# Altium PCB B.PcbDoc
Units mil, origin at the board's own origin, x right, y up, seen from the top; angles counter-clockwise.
Board outline 3543 x 2362 mil, 4 copper layers (Top Layer, Internal Plane 1, Internal Plane 2, Bottom Layer); 34 components, 28 nets, 139 pads, 8 vias.
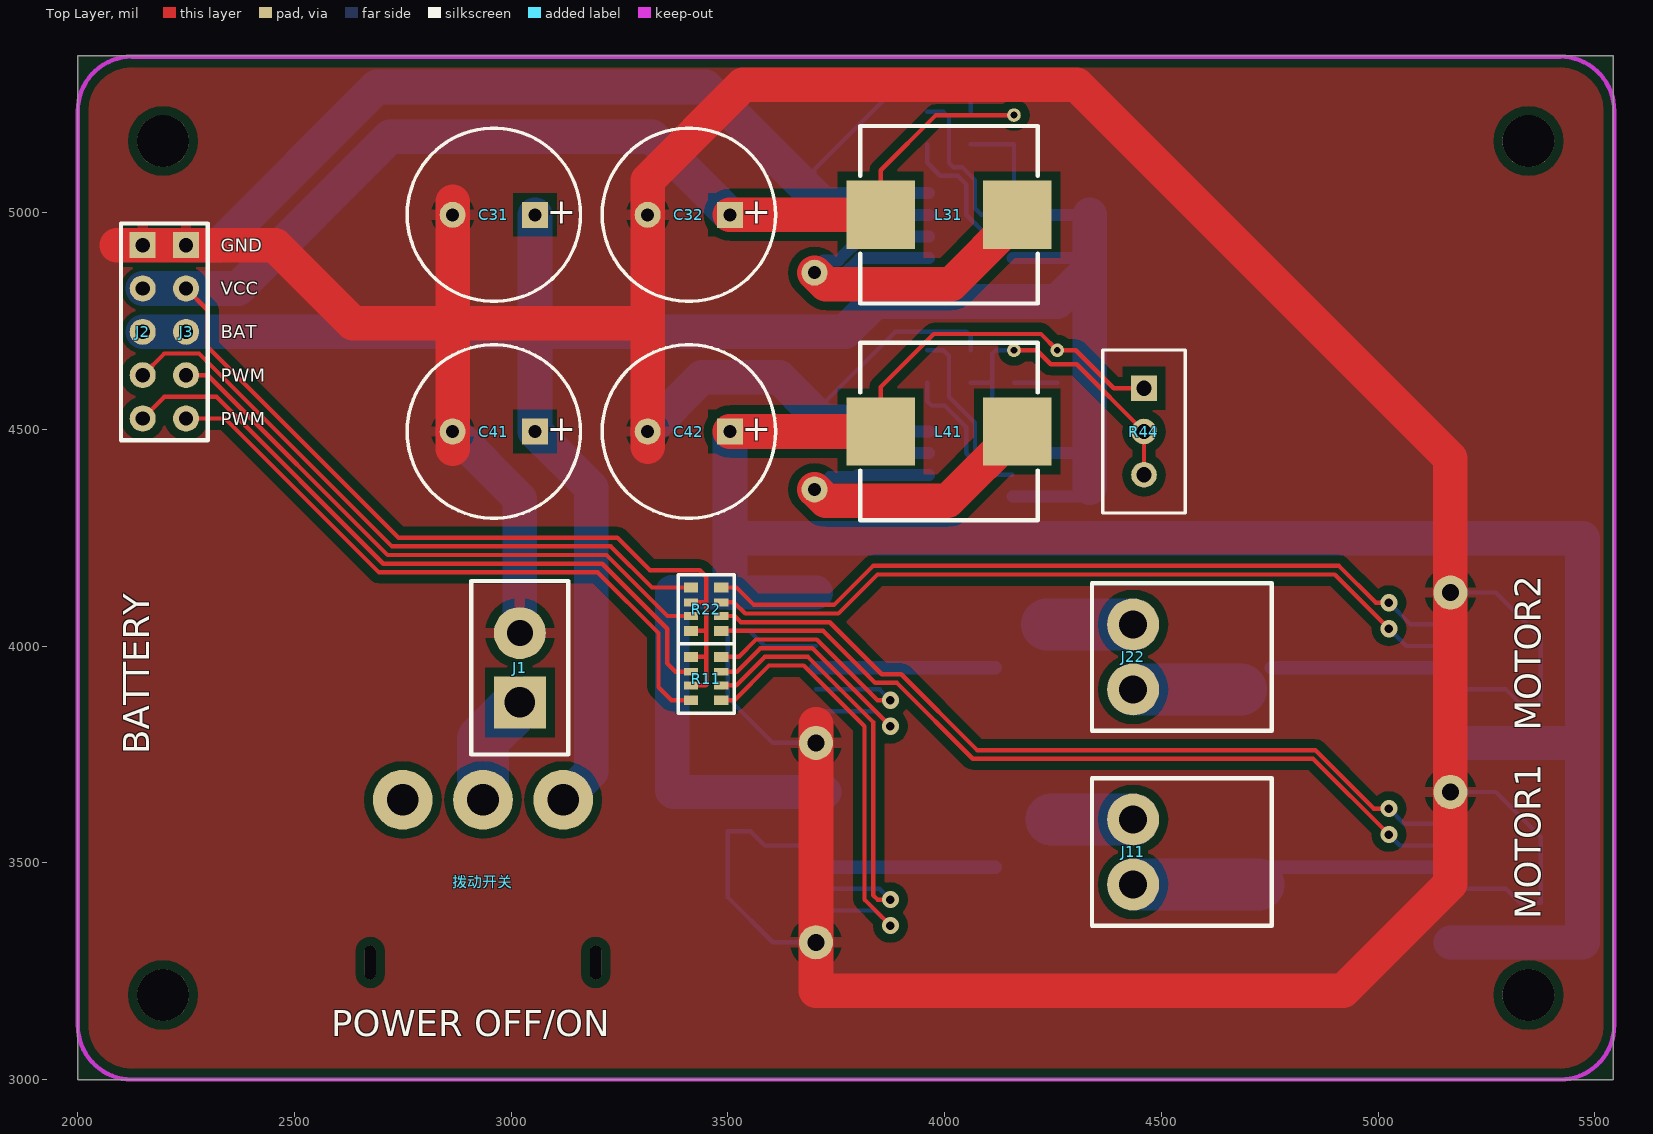
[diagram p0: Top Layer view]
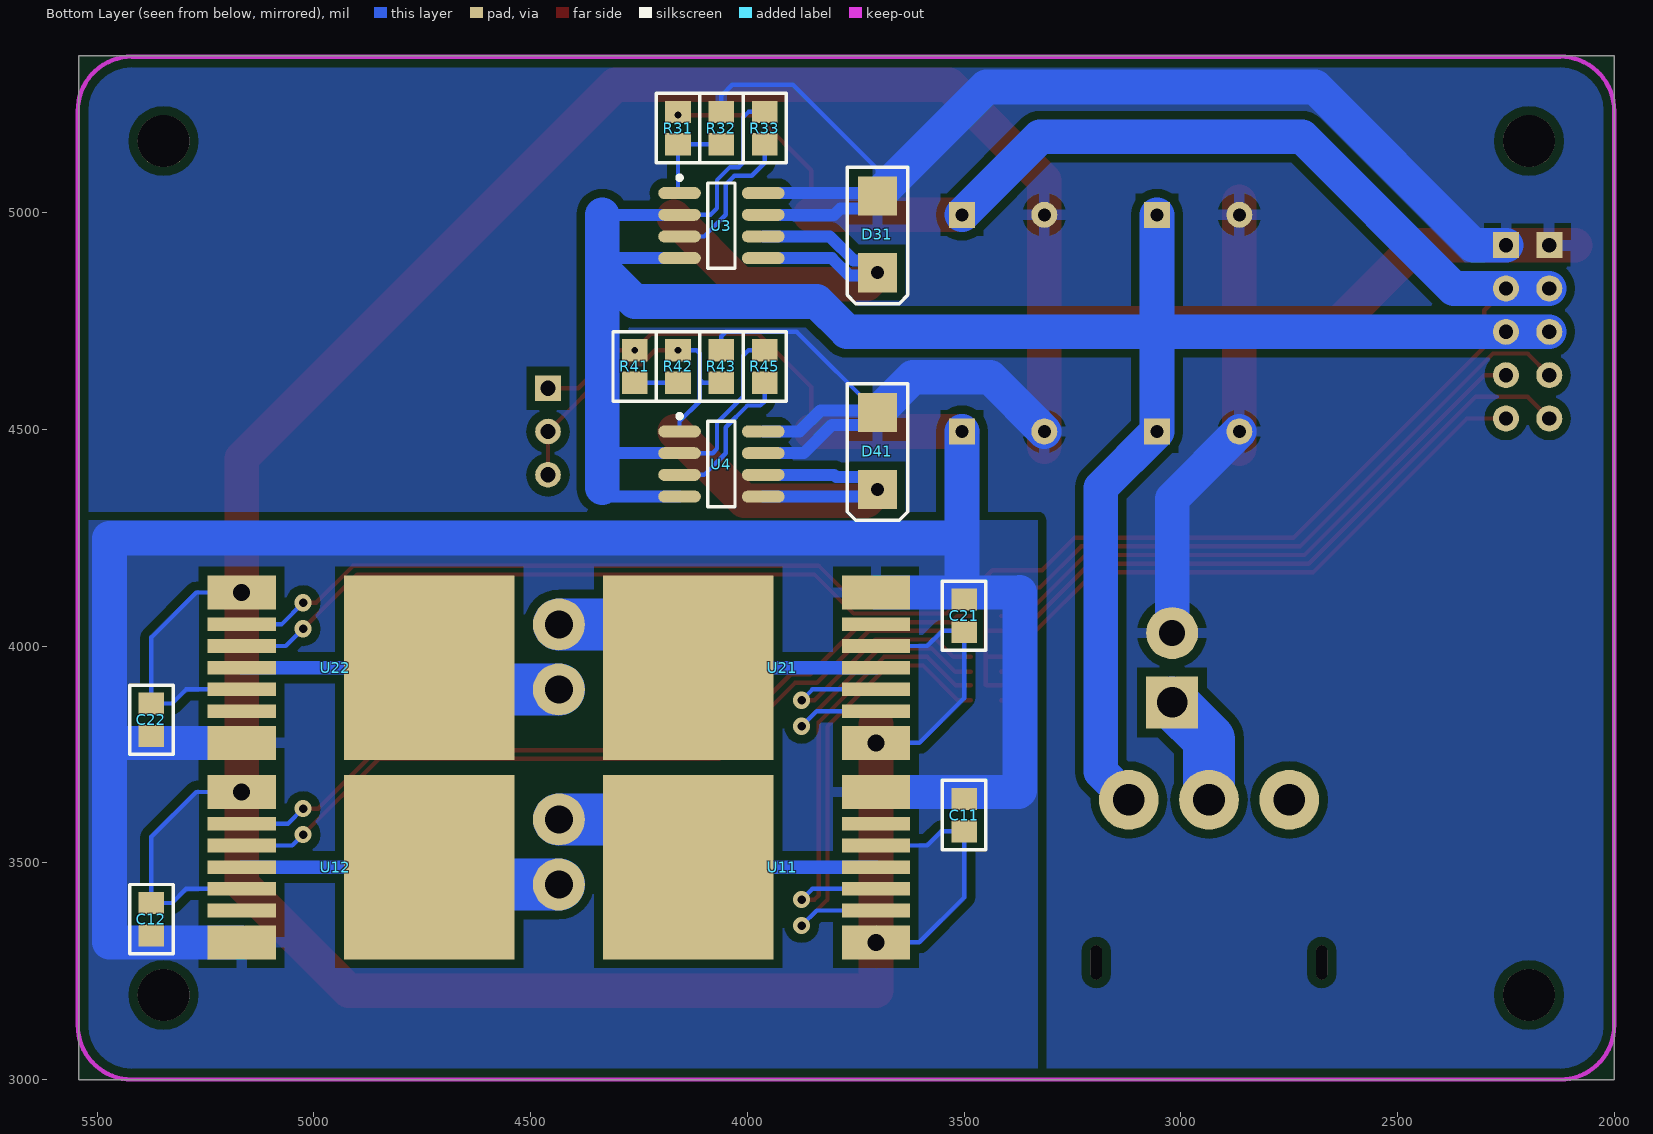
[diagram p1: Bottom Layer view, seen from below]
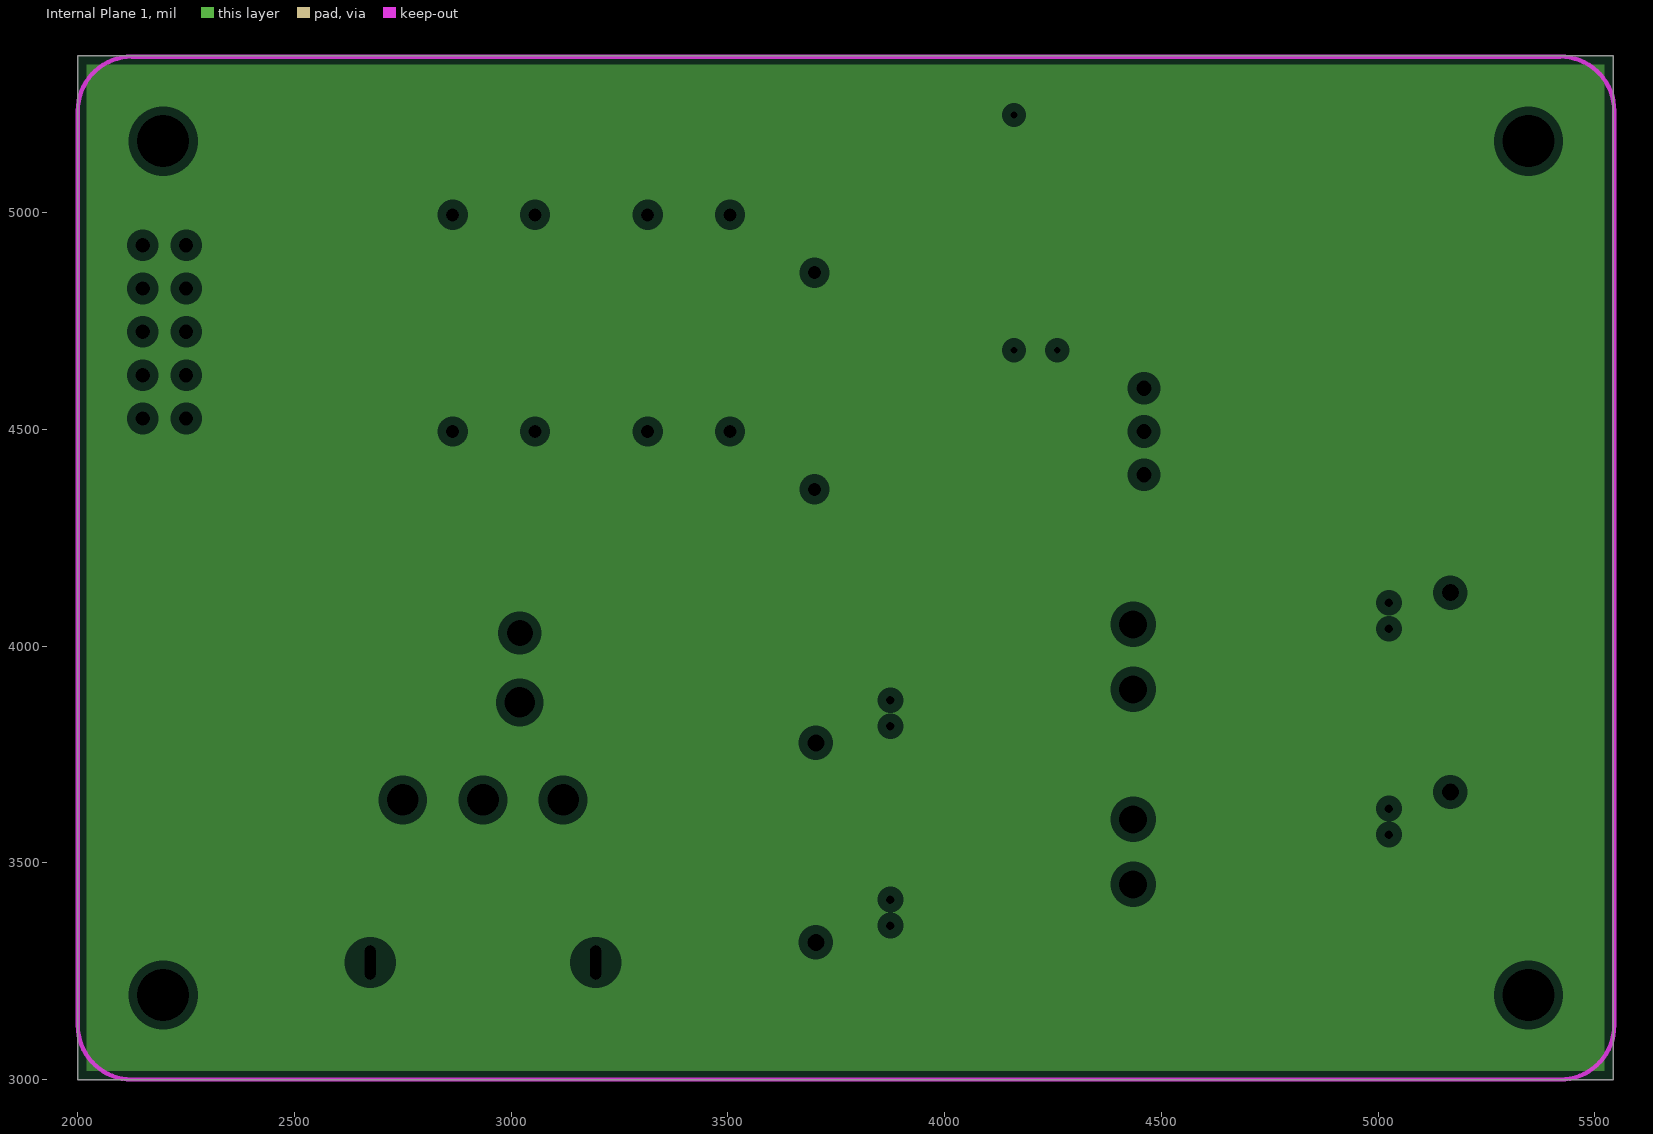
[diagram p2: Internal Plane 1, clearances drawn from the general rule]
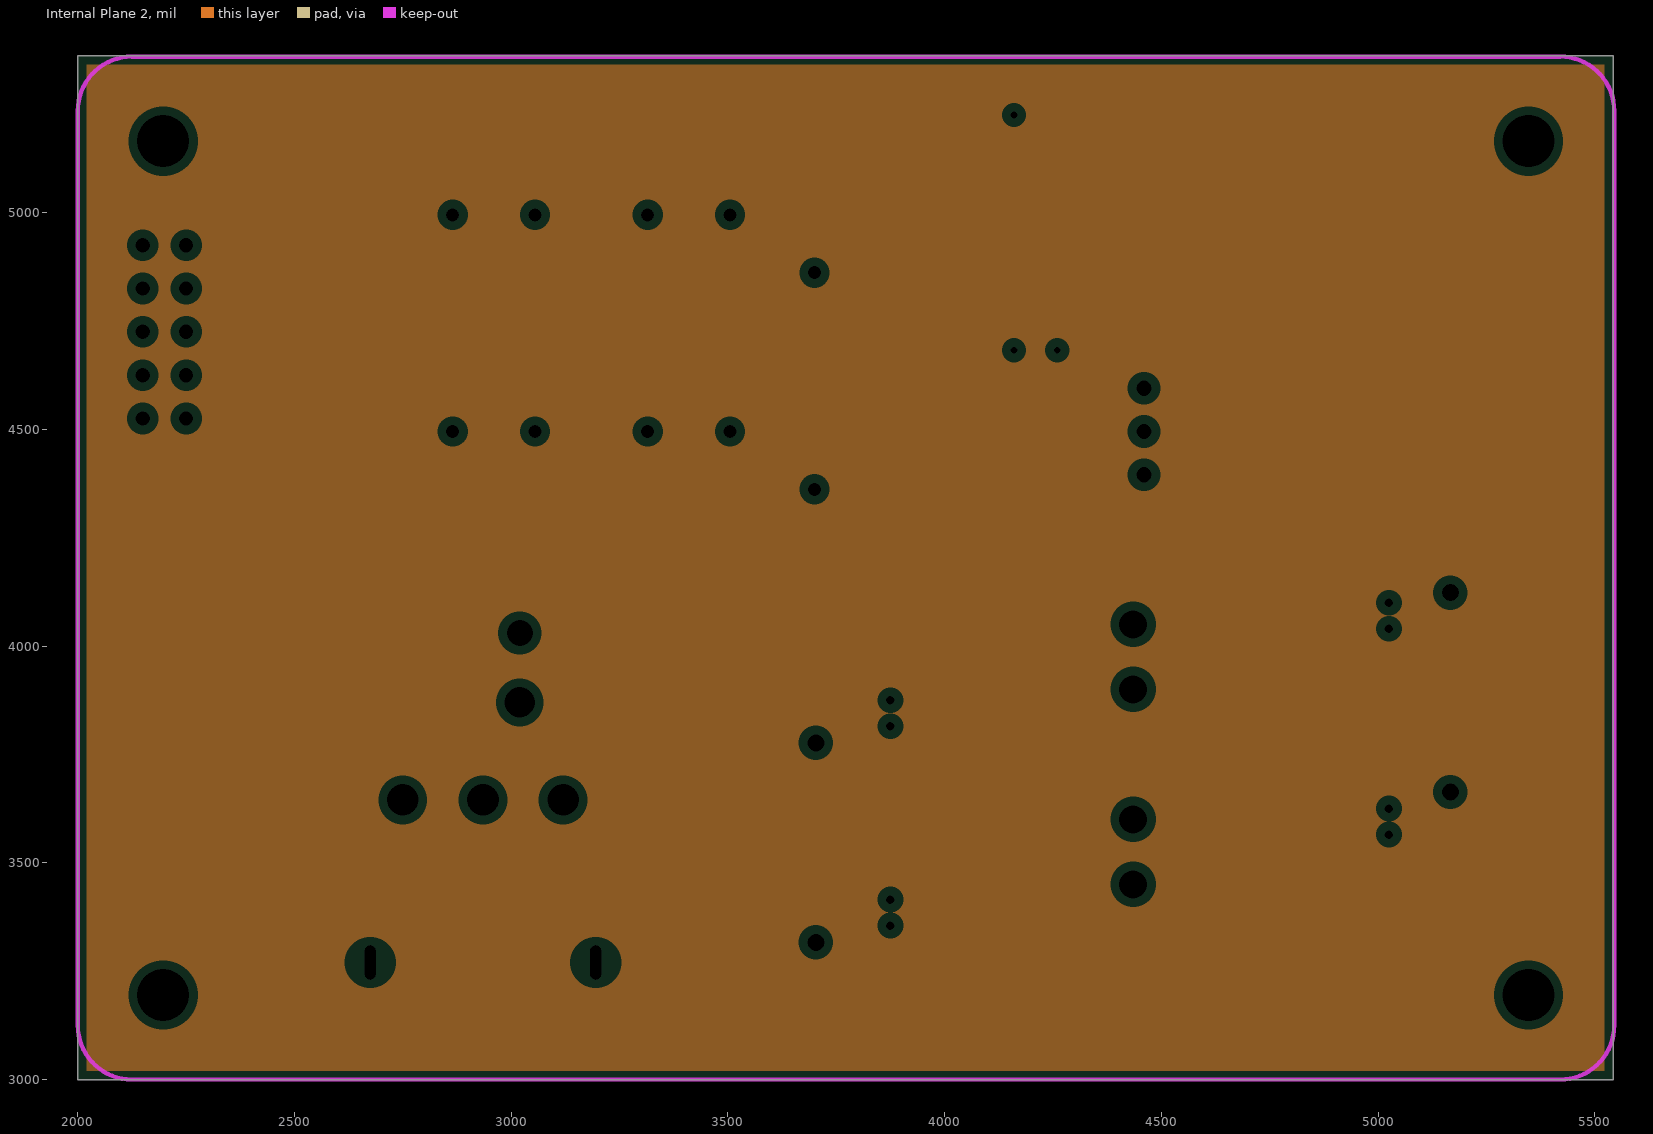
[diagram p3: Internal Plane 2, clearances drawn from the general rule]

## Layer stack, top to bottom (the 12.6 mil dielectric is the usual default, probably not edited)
Top Layer: signal copper 1.4
Dielectric: dielectric 12.6, FR-4, Dk 4.8
Internal Plane 1: plane copper 1.4
Dielectric: dielectric 12.6, FR-4, Dk 4.8
Internal Plane 2: plane copper 1.4
Dielectric: dielectric 12.6, FR-4, Dk 4.8
Bottom Layer: signal copper 1.4

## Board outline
2000,3000 5543,3000 5543,5362 2000,5362

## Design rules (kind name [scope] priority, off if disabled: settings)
Clearance Clearance_1 [InComponent('U1')] p1: gap=7
Clearance Clearance_2 [InPolygon] p2: gap=20
Clearance [All] p3: gap=5
ComponentClearance [All] p1: gap=0 collisioncheckmode=3 verticalgap=0 showdistances=FALSE
HoleSize [All] p1: absolutevalues=TRUE maxlimit=150 minlimit=1 maxpercent=80.000 minpercent=20.000
MinimumSolderMaskSliver [All] p1: minsoldermaskwidth=0
PlaneClearance [All] p1: clearance=20
PlaneConnect [All] p1: planeconnectstyle=Relief reliefexpansion=20 reliefentries=4 reliefconductorwidth=10 reliefairgap=10
PolygonConnect [All] p1: connectstyle=Relief reliefconductorwidth=25 reliefentries=4 polygonreliefangle="90 Angle"
RoutingVias [All] p1: holewidth=23 width=37 viastyle="Through Hole" minholewidth=10 minwidth=20 maxholewidth=150 maxwidth=150
SilkToSilkClearance [All] p1: silktosilkclearance=0
SilkscreenOverComponentPads [All] p1: minsilkscreentomaskgap=5
SolderMaskExpansion [All] p1: expansion=0
Width [All] p1: maxlimit=120 minlimit=9 preferedwidth=10
21 further rules are at their usual default settings.

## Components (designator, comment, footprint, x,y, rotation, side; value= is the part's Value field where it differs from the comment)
C11 "470nF" 0805 3500,3610 r90 bottom
C12 "470nF" 0805 5375,3370 r270 bottom
C21 "470nF" 0805 3500,4070 r270 bottom
C22 "470nF" 0805 5375,3830 r90 bottom
C31 "470uF/25V" CAPPR0.19 2960,4995 r180 top
C32 "330uF/16V" CAPPR0.19 3410,4995 r180 top
C41 "470uF/25V" CAPPR0.19 2960,4495 r180 top
C42 "330uF/16V" CAPPR0.19 3410,4495 r180 top
D31 "SK54" SMC/DO-214AB 3700,4950 r270 bottom
D41 "SK54" SMC/DO-214AB 3700,4450 r270 bottom
J1 "电源接口" DC12V 3020,3950 r90 top
J2 "5 端口" SIP5 2150,4725 r270 top
J3 "5 端口" SIP5 2250,4725 r270 top
J11 "马达接口" MOTOR-W 4435,3525 r270 top (schematic designator J1)
J22 "马达接口" MOTOR-W 4435,3975 r270 top (schematic designator J2)
L31 "15uH" 4040电感 4010,4995 r180 top
L41 "10uH" 4040电感 4010,4495 r180 top
R11 "10K" PZ-4 3450,3925 r270 top
R22 "10K" PZ-4 3450,4085 r270 top
R31 "6.8K" 0805 4160,5195 r90 bottom
R32 "1.3K" 0805 4060,5195 r270 bottom
R33 "2.7K" 0805 3960,5195 r90 bottom
R41 "270" 0805 4260,4645 r90 bottom
R42 "10K" 0805 4160,4645 r270 bottom
R43 "1K" 0805 4060,4645 r270 bottom
R44 "20K" 电位器 4460,4495 r270 top
R45 "2.7K" 0805 3960,4645 r90 bottom
U3 "AS1015" SOP8_M 4060,4970 r180 bottom
U4 "AS1015" SOP8_M 4060,4420 r180 bottom
U11 "BTN7971B" TO263-7-1 3900,3490 r90 bottom
U12 "BTN7971B" TO263-7-1 4970,3490 r270 bottom
U21 "BTN7971B" TO263-7-1 3900,3950 r90 bottom
U22 "BTN7971B" TO263-7-1 4970,3950 r270 bottom
拨动开关 "开关" 5A120V开关 2935,3270 r0 top

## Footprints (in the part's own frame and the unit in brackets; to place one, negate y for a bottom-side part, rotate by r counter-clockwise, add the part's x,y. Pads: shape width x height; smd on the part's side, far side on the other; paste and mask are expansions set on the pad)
5A120V开关 [mm]
  round 3.5 hole 1.85: 1(0,9.53) 2(4.7,9.53) ""(-4.7,9.53)
  oval 0.66x2 hole 0.66 slot 2 at 90 deg: ""(-6.605,0) ""(6.605,0)
0805 [mm]
  rect 1.3x1.5 smd: 1(-0.95,0) 2(0.95,0)
  silkscreen extent -2.03,-1.27 2.03,1.27
4040电感 [mm]
  rect 4x4 smd: 1(-4,0) 2(4,0)
  silkscreen extent -5.2,-5.2 5.2,5.2
CAPPR0.19 [mil]
  rect 60x60 hole 30: 1(-95,0)
  round 60 hole 30: 2(95,0)
  silkscreen extent -200,-200 200,200
DC12V [mil]
  rect 120x120 hole 70: 1(-80,0)
  round 120 hole 60: 2(80,0)
  silkscreen extent -200,-112 200,112
MOTOR-W [mil]
  round 120 hole 65: 1(-75,0) 2(75,0)
  silkscreen extent -170,-95 170,320
PZ-4 [mm]
  rect 0.58x0.835 smd: 1(-1.27,-0.887) 4(1.27,-0.887) 5(1.27,0.887) 8(-1.27,0.887)
  rect 0.457x0.835 smd: 2(-0.4,-0.887) 3(0.4,-0.887) 6(0.4,0.887) 7(-0.4,0.887)
  silkscreen extent -2.03,-1.65 2.03,1.65
SIP5 [mil]
  rect 60x60 hole 33: 1(-200,0)
  round 60 hole 33: 2(-100,0) 3(0,0) 4(100,0) 5(200,0)
SMC/DO-214AB [mm]
  rect 2.3x2.3 smd: 1(-2.25,0) 2(2.25,0)
  silkscreen extent -3.94,-1.78 4.06,1.78
SOP8_M [mm] "SOIC, 8-Leads, Body 4.9x3.9mm, Pitch 1.27mm, IPC Low Density"
  oval 2.5x0.7 smd: 1(-2.45,1.905) 2(-2.45,0.635) 3(-2.45,-0.635) 4(-2.45,-1.905) 5(2.45,-1.905) 6(2.45,-0.635) 7(2.45,0.635) 8(2.45,1.905)
  silkscreen extent -2.58,-2.5 0.8,2.93
TO263-7-1 [mm]
  rect 1.99x4 smd: 1(-4.405,-5) 7(4.405,-5)
  rect 0.8x4 smd: 2(-2.54,-5) 3(-1.27,-5) 4(0,-5) 5(1.27,-5) 6(2.54,-5)
  rect 10.8x10 smd: 4(0,6)
  Top Layer lines w0.8: 0,-5 0,5.5
电位器 [mm]
  rect 1.5x1.5 hole 0.9: 1(-2.54,0)
  round 1.5 hole 0.9: 2(0,0) 3(2.54,0)
  silkscreen extent -4.78,-2.41 4.78,2.41

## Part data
C31 C32 C41 C42: library part C+
D31 D41: library part D
J1: library part µçÔ´½
J2 J3: library part "5 ¶Ë¿"
J11 J22: library part 马达
R11 R22: library part "Res Pack", "Isolated Resistor Network - Pa"
R31 R32 R33 R41 R42 R43 R45: library part R
R44: library part 可变电阻, "Potenti"
U11 U12 U21 U22: library part BTN79

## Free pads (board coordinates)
  round 120 hole 120: 0(2197,3195) 0(2197,5165) 0(5347,3195) 0(5347,5165)
  round 60 hole 30: 0(3700,4361.42) 0(3700,4861.42)
  round 78.74 hole 39.37: 0(3703.15,3316.57) 0(3703.15,3776.57) 0(5166.85,3663.43) 0(5166.85,4123.43)
  round 31.5 hole 15.75: 1(4160,5225) 1(4260,4682.4) 2(4160,4682.4)

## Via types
v1: diameter 39.37, hole 19.68, Top Layer to Bottom Layer, 8 vias

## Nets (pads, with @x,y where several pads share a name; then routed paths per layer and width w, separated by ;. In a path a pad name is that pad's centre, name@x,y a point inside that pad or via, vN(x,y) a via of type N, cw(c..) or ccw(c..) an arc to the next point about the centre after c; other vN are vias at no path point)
ADJ: C11.2 C12.2 C21.1 C22.1 C42.1 L41.2 pad.1@4260,4682.4 R41.2 R44.1 U11.7 U12.7 U21.7 U22.7 | length 6170
  Top Layer w10: L41.2 3852.52,4597.52 3975,4720 4222.4,4720 4260,4682.4 4302.6,4682.4 4390,4595 R44.1
  Top Layer w80: C42.1 L41.2
  Bottom Layer w78.35: 3371.57,3666.85 3375,3663.43 U11.7 U11.7@3722.83,3663.43 ; 3371.57,4123.43 3505,4123.43 U21.7 ; U12.7 5471.57,3316.57 ; U22.7@5177.17,3776.57 5471.57,3776.57
  Bottom Layer w80: 3371.57,3666.85 3371.57,4123.43 ; C21.1@3505,4123.43 3505,4248.43 ; C42.1 3505,4248.43 ; 5471.57,3316.57 5471.57,3776.57 5471.57,4248.43 3505,4248.43
BAT: J1.1 拨动开关.1 | length 260
  Bottom Layer w120: 拨动开关.1 2935,3785 J1.1
GND: C11.1 C12.1 C21.2 C22.2 C31.2 C32.2 C41.2 C42.2 D31.1 D41.1 J1.2 J2.1 J3.1 pad.0@3703.15,3316.57 pad.0@3703.15,3776.57 pad.0@5166.85,3663.43 pad.0@5166.85,4123.43 R32.1 R43.1 U3.7 U3.8 U4.7 U4.8 U11.1 U11.5 U12.1 U12.5 U21.1 U21.5 U22.1 U22.5 | length 15122.9
  Top Layer w80: 2090,4925 J3.1 2455,4925 2635,4745 2865,4745 ; 2865,4455 C41.2 2865,4745 ; 2865,5025 2865,4745 ; 3315,4460 3315,4745 ; 3703.15,3820 3703.15,3316.57 3703.15,3205 4920,3205 5166.85,3451.85 5166.85,3663.43 5166.85,4123.43 5166.85,4433.15 4305,5295 3535,5295 3315,5075 3315,4745 ; 2865,4745 3315,4745
  Bottom Layer w10: C21.2 3500,3880 3603.43,3776.57 U21.1 ; C21.2@3502.4,4035 3550,4035 3585,4000 U21.5 ; D41.1 3886.42,4725 4050,4725 4060,4715 R43.1 ; D31.1@3700,5045 3700,5100 3895,5295 4035,5295 4060,5270 R32.1 ; U11.1 3603.43,3316.57 3500,3420 C11.1 3552.4,3572.6 3585,3540 U11.5 ; D41.1@3735,4543.58 D41.1@3735,4555 ; U12.1 5271.57,3663.43 5375,3560 C12.1 5327.6,3407.4 5295,3440 U12.5@5196.85,3440 ; U22.1 5271.57,4123.43 5375,4020 C22.2 5327.6,3867.4 5295,3900 U22.5@5196.85,3900
  Bottom Layer w27.56: D31.1@3700,5045 U3.8 ; D31.1@3715,5010 3785,5010 3800,4995 U3.7 ; D41.1@3735,4510 3805,4510 3870,4445 U4.7 ; D41.1@3735,4543.58 3831.42,4543.58 3880,4495 U4.8
  Bottom Layer w80: J3.1 2325,4925 2690,5290 3448.58,5290 D31.1 ; C41.2 3020,4340 J1.2 ; C42.2 3440,4620 3618.58,4620 D41.1
M1A: J11.1 U11.4 | length 188.8
  Bottom Layer w120: U11.4@4246.22,3600 J11.1
M1B: J11.2 U12.4 | length 288.8
  Bottom Layer w120: J11.2 U12.4@4723.78,3450
M2A: J22.1 U21.4 | length 198.8
  Bottom Layer w120: U21.4@4236.22,4050 J22.1
M2B: J22.2 U22.4 | length 248.8
  Bottom Layer w120: J22.2 U22.4@4683.78,3900
NetD31_2: D31.2 L31.1 pad.0@3700,4861.42 U3.5 U3.6 | length 1056.6
  Top Layer w80: pad.0@3700,4861.42 3726.42,4835 4015,4835 L31.1@4170,4990
  Bottom Layer w27.56: D31.2@3720,4890 3755,4890 3810,4945 U3.6 ; D31.2@3735,4855 3765,4855 3805,4895 U3.5
NetD41_2: D41.2 L41.1 pad.0@3700,4361.42 U4.5 U4.6 | length 998.9
  Top Layer w80: pad.0@3700,4361.42 3726.42,4335 4007.48,4335 L41.1
  Bottom Layer w27.56: D41.2@3735,4390 3795,4390 3800,4395 U4.6 ; D41.2@3740,4345 U4.5
NetR11_5: R11.5 U11.2 | length 1092.4
  Top Layer w10: R11.5 3515,3875 3595,3955 3675,3955 3815,3815 3815,3415 v1(3875,3355)
  Bottom Layer w10: U11.2 3840,3390 v1(3875,3355)
NetR11_6: R11.6 U11.3 | length 1065.8
  Top Layer w10: R11.6 3519.25,3909.25 3585,3975 3685,3975 3835,3825 3835,3425 3845,3415 v1(3875,3415)
  Bottom Layer w10: U11.3 3850,3440 v1(3875,3415)
NetR11_7: R11.7 U21.2 | length 673.5
  Top Layer w10: R11.7 3520.75,3940.75 3575,3995 3695,3995 v1(3875,3815)
  Bottom Layer w10: U21.2 3840,3850 v1(3875,3815)
NetR11_8: R11.8 U21.3 | length 646.8
  Top Layer w10: R11.8 3525,3975 3565,4015 3705,4015 3845,3875 v1(3875,3875)
  Bottom Layer w10: U21.3 3850,3900 v1(3875,3875)
NetR22_5: R22.5 U12.3 | length 1887
  Top Layer w10: R22.5 3720,4035 3840,3915 3890,3915 4065,3740 4850,3740 v1(5025,3565)
  Bottom Layer w10: v1(5025,3565) 5050,3540 U12.3
NetR22_6: R22.6 U12.2 | length 1880.4
  Top Layer w10: R22.6 3515.75,4069.25 3530,4055 3735,4055 3855,3935 3900,3935 4075,3760 4855,3760 4990,3625 v1(5025,3625)
  Bottom Layer w10: v1(5025,3625) 5060,3590 U12.2
NetR22_7: R22.7 U22.3 | length 1798.2
  Top Layer w10: R22.7 3514.25,4100.75 3540,4075 3755,4075 3845,4165 4900,4165 v1(5025,4040)
  Bottom Layer w10: v1(5025,4040) 5065,4000 U22.3
NetR22_8: R22.8 U22.2 | length 1801.7
  Top Layer w10: R22.8 3520,4135 3560,4095 3745,4095 3835,4185 4910,4185 4995,4100 v1(5025,4100)
  Bottom Layer w10: v1@5035,4100 v1(5025,4100) 5075,4050 U22.2
NetR31_1: R31.1 R32.2 U3.1 | length 209.1
  Bottom Layer w10: R32.2 R31.1 U3.1@4160,5048.54
NetR33_1: R33.1 U3.3 | length 350.5
  Bottom Layer w10: R33.1 3960,5115 3990,5085 4030,5085 4050,5065 4050,4995 4100,4945 U3.3
NetR41_1: R41.1 R42.2 | length 100
  Bottom Layer w10: R42.2 R41.1
NetR42_1: pad.2 R42.1 R43.2 R44.2 R44.3 U4.1 | length 783
  Top Layer w10: pad.2 4212.6,4682.4 4245,4650 4305,4650 R44.2 R44.3
  Bottom Layer w10: R43.2 4102.6,4607.6 4110,4615 ; U4.1 4156.46,4518.54 4110,4565 4110,4615 ; pad.2 4117.4,4682.4 4110,4675 4110,4615
NetR45_1: R45.1 U4.3 | length 344.6
  Bottom Layer w10: R45.1 3960,4565 3970,4555 4000,4555 4050,4505 4050,4445 4100,4395 U4.3
PWM1: J3.5 R11.4 | length 1507.5
  Top Layer w10: J3.5 2340,4525 2695,4170 3200,4170 3340,4030 3340,3905 3370,3875 R11.4
PWM2: J3.4 R22.3 | length 1395.3
  Top Layer w10: J3.4 2300,4625 2715,4210 3220,4210 3360.75,4069.25 R22.3
PWM3: J2.5 R11.2 | length 1595.4
  Top Layer w10: J2.5 2200,4575 2320,4575 2705,4190 3210,4190 3360,4040 3360,3960 3379.25,3940.75 R11.2
PWM4: J2.4 R22.1 | length 1509.5
  Top Layer w10: J2.4 2200,4675 2280,4675 2725,4230 3230,4230 3325,4135 R22.1
VCC: C32.1 J2.2 J3.2 L31.2 pad.1@4160,5225 R11.1 R11.3 R22.2 R22.4 R31.2 | length 4302.6
  Top Layer w10: J3.2 2300,4775 2300,4690 2740,4250 3245,4250 3320,4175 3435,4175 3450,4160 3450,4100.75 ; R11.3 3449.25,3909.25 3450,3910 3450,3975 ; R11.1 3450,3975 ; R22.4 3450,4035 ; R22.2 3450,4100.75 ; L31.2 3852.52,5097.52 3980,5225 pad.1@4160,5225 ; 3450,3975 3450,4035 ; 3450,4035 3450,4100.75
  Top Layer w80: C32.1 L31.2 L31.2@3855,4995
  Bottom Layer w80: J2.2 J3.2 2370,4825 2720,5175 3325,5175 C32.1
VIN: C31.1 C41.1 J2.3 J3.3 R33.2 R45.2 U3.2 U3.4 U4.2 U4.4 拨动开关.2 | length 5711.2
  Bottom Layer w10: R45.2 3997.6,4682.4 4010,4670 4010,4575 4070,4515 4070,4455 4080,4445 U4.2 ; R33.2 3997.6,5232.4 4010,5220 4010,5115 4020,5105 4040,5105 4070,5075 4070,5010 4085,4995 U3.2
  Bottom Layer w27.56: U4.4 4335,4345 ; U4.2 4335,4445 ; U3.4 4310,4895 ; U3.2 4335,4995
  Bottom Layer w80: J2.3 J3.3 3770,4725 3840,4795 4260,4795 4335,4870 ; C31.1 C41.1 3185,4365 3185,3710.16 拨动开关.2@3165,3690.16 ; 4335,4365 4335,4445 4335,4870 ; 4335,4995 4335,4870
pads on no net: U11.6 U12.6 U21.6 U22.6 拨动开关.

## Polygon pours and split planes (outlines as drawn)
GND on Bottom Layer "Bottom Layer-No Net" (solid, remove dead copper, pour order 52): 1745,5465 5680,5465 5775,5560 5615,5400 5615,2830 1655,2830
ADJ on Bottom Layer "Bottom Layer-No Net" (solid, remove dead copper, pour order 50): 3330,4290 5615,4290 5605,4280 5605,2895 3360,2895 3325,2860 3330,2855
GND on Top Layer "Bottom Layer-No Net" (solid, remove dead copper, pour order 54): 1875,5495 1880,5500 5640,5500 5640,2925 5625,2910 5620,2915 1845,2915
no net on Internal Plane 1 (split plane): 5522.9,3020.1 2020.1,3020.1 2020.1,5341.9 5522.9,5341.9
no net on Internal Plane 2 (split plane): 5522.9,3020.1 2020.1,3020.1 2020.1,5341.9 5522.9,5341.9

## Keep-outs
Keep-Out Layer:
  lines w10: 2000,3125 ccw(c2125,3125) 2125,3000 5420,3000 ccw(c5420,3125) 5545,3125 5545,5235 ccw(c5420,5235) 5420,5360 2125,5360 ccw(c2125,5235) 2000,5235 2000,3125

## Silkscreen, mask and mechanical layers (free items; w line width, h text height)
Top Overlay:
  lines w10: 2100,4475 2100,4975 2300,4975 2300,4475 2100,4475
  text "GND" at 2330,4910 h30
  text "VCC" at 2330,4810 h30
  text "BAT" at 2330,4710 h30
  text "PWM" at 2330,4610 h30
  text "PWM" at 2330,4510 h30
  text "MOTOR2" at 5375,3805 h60 r90
  text "BATTERY" at 2165,3750 h60 r90
  text "MOTOR1" at 5375,3370 h60 r90
  text "POWER OFF/ON" at 2585,3100 h60
Drill Drawing:
  text ".LEGEND" at -922,3165 h60
  text "Drill Drawing." at -922,3065 h60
